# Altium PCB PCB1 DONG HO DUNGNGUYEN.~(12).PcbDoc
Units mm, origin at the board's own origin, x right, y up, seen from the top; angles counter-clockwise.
Board outline 60.96 x 45.72 mm, 2 copper layers (Top Layer, Bottom Layer); 7 components, 8 nets, 31 pads, 0 vias.
Unrouted connection lines stored in the file: 6.
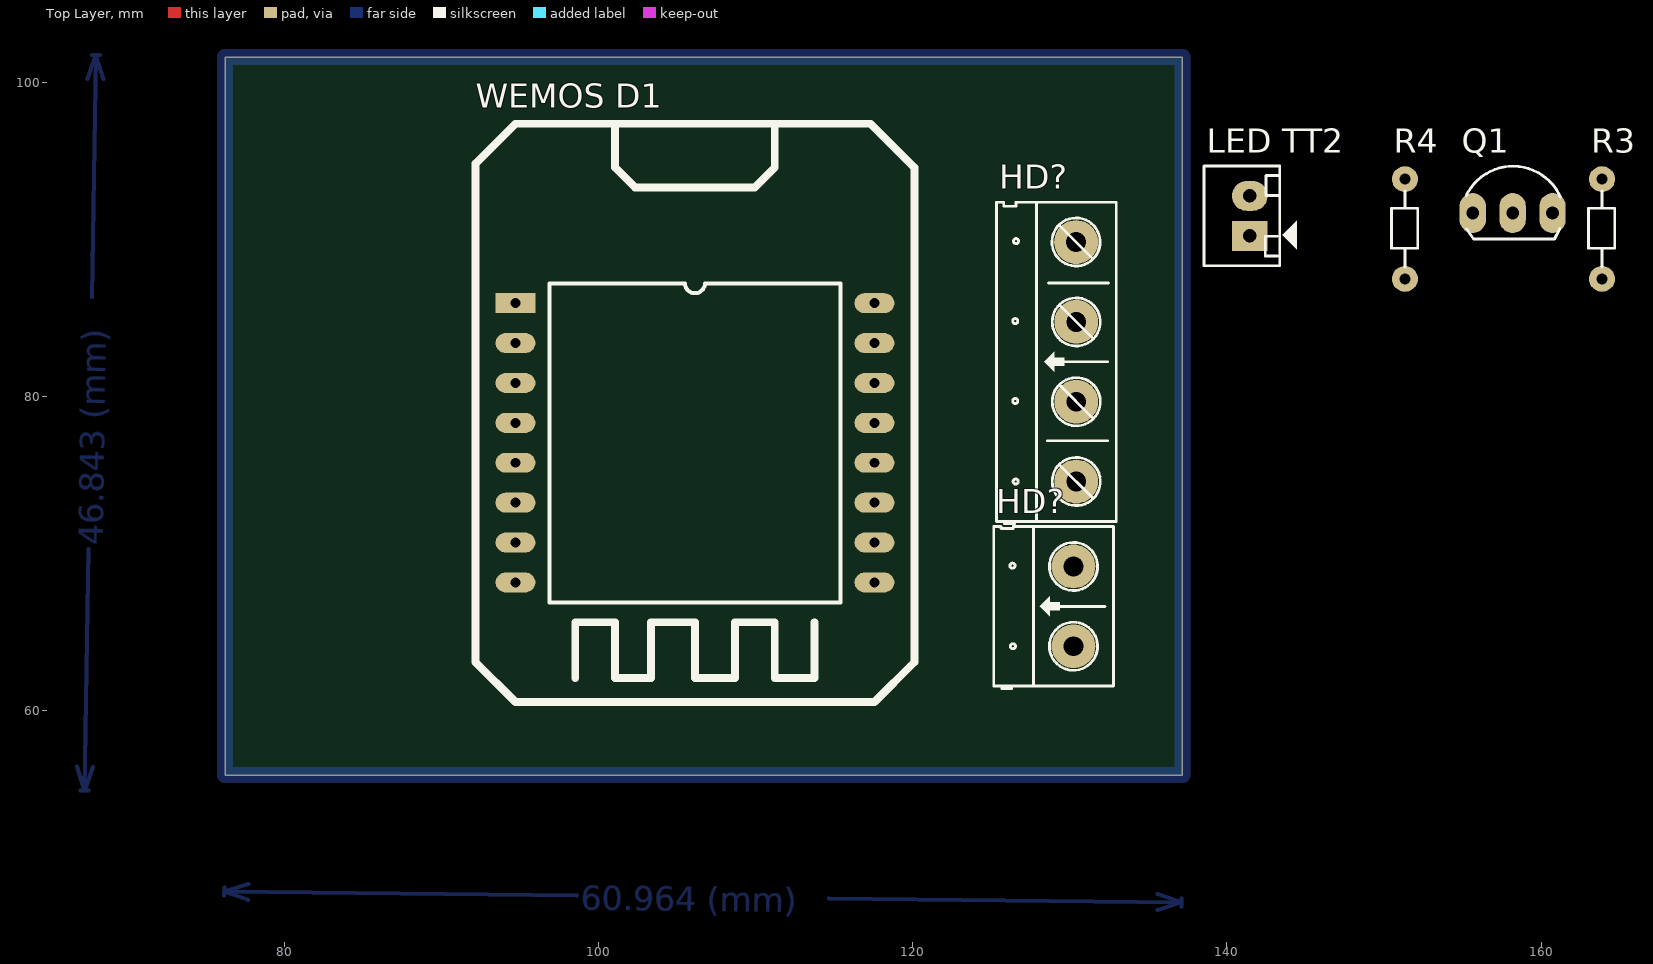
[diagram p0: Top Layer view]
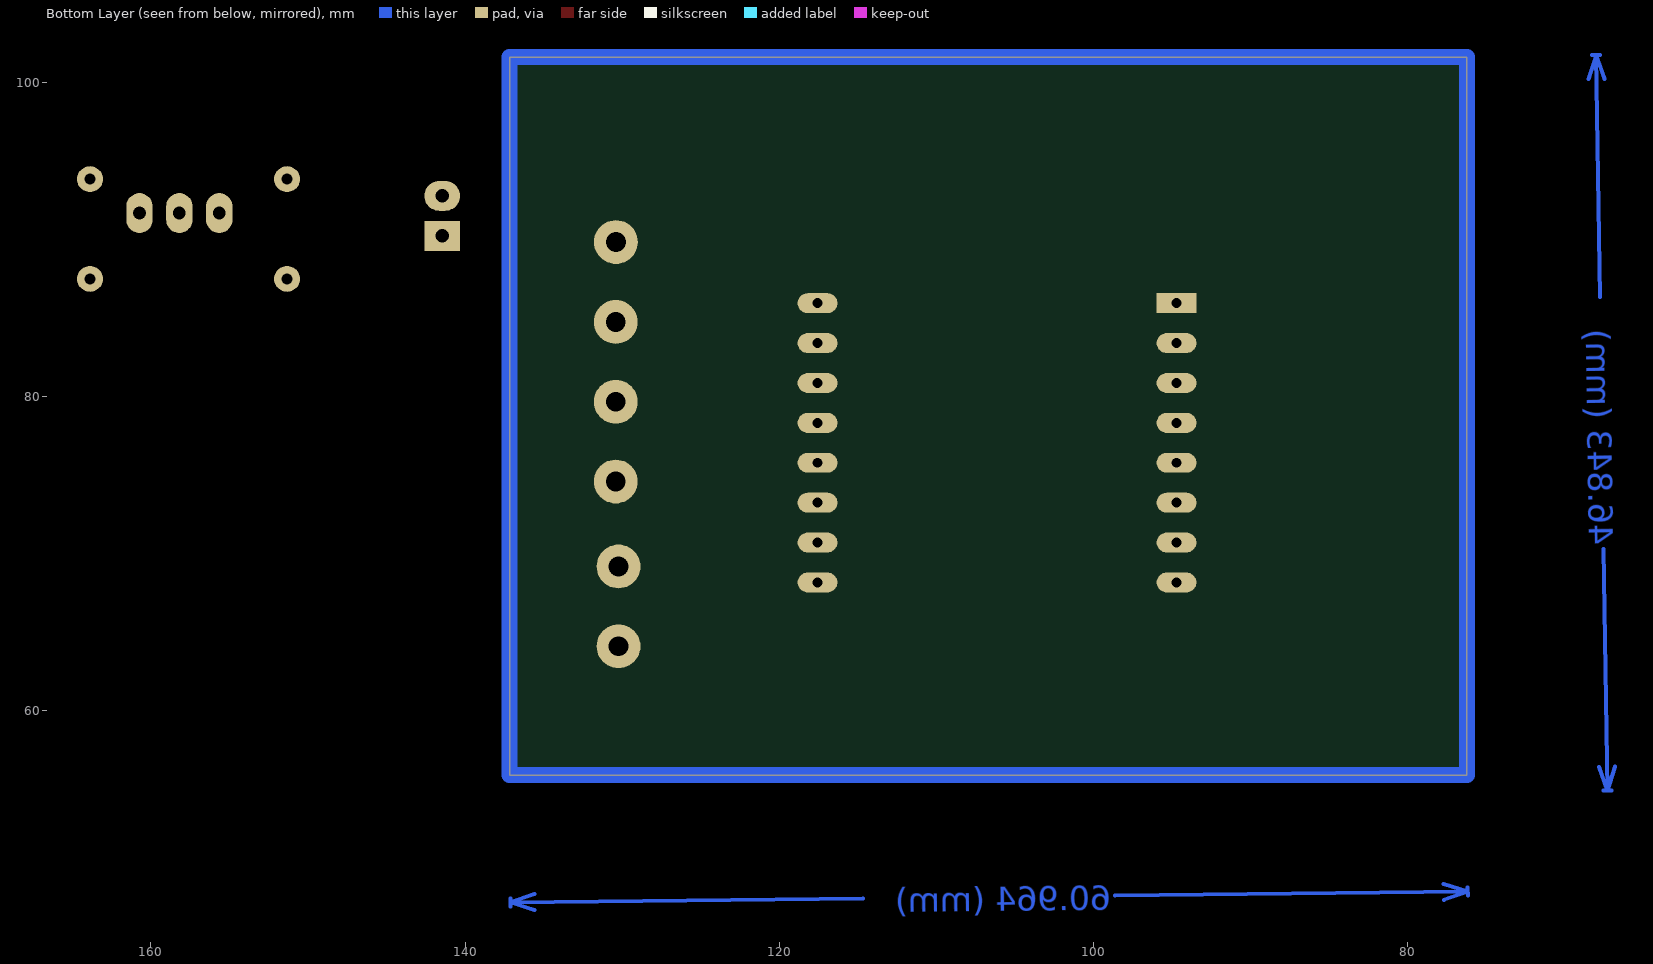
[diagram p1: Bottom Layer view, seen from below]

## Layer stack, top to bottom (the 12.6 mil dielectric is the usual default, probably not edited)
Top Solder: solder mask 0.0102, Solder Resist, Dk 3.5
Top Layer: signal copper 0.0356
Dielectric 1: dielectric 0.32, FR-4, Dk 4.8
Bottom Layer: signal copper 0.0356
Bottom Solder: solder mask 0.0102, Solder Resist, Dk 3.5

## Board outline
76.2,55.88 76.2,101.6 137.16,101.6 137.16,55.88

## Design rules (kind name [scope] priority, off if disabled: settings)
Clearance [All] p1: gap=0.254 ignorepadtopadclearanceinfootprint=FALSE except(0: Arc-Hole Track-Hole SMDPad-Hole THPad-Hole Via-Hole Fill-Hole Poly-Hole Region-Hole Text-Hole)
PolygonConnect [All] p1: connectstyle=Relief reliefconductorwidth=0.254 reliefentries=4 polygonreliefangle="90 Angle" airgapwidth=0.254
RoomDefinition DONG_HO [InComponentClass('DONG_HO')] p1: confinementstyle=ConfineIn formatcopy=TRUE lockcomponents=FALSE outline 138.303,57.277 149.25,57.277 149.25,67.132 138.303,67.132
RoutingVias [All] p1: holewidth=0.711 width=1.27 viastyle="Through Hole" minholewidth=0.711 minwidth=1.27 maxholewidth=2.54 maxwidth=2.54
SolderMaskExpansion [All] p1: expansion=0.102
Width [All] p1: maxlimit=2.032 minlimit=1.016 preferedwidth=1.524
30 further rules are at their usual default settings.

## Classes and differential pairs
component class DONG_HO: HD? "LED TT2" Q1 R3 R4 "WEMOS D1"

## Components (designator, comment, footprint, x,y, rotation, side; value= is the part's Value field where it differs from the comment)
HD? "Header 4" HED4 130.404,74.574 r90 top
HD? "Header 2" HED2 130.226,64.084 r90 top
"LED TT2" "Header2" Header2 141.453,90.221 r90 top
Q1 "C1815" QTO-92 158.191,91.669 r0 top
R3 "100" RES-1/8W-SMALL 163.881,90.653 r90 top
R4 "Res" RES-1/8W-SMALL 151.333,90.653 r90 top
"WEMOS D1" "Component_1" "ESP WEMOS MINI" 94.691,85.928 r0 top

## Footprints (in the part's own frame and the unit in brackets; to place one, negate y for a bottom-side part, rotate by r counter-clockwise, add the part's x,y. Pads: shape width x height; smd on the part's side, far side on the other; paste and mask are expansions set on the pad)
"ESP WEMOS MINI" [mm]
  rect 2.54x1.27 hole 0.635: 1(0,0)
  oval 2.54x1.27 hole 0.635: 2(0,-2.54) 3(0,-5.08) 4(0,-7.62) 5(0,-10.16) 6(0,-12.7) 7(0,-15.24) 8(0,-17.78) 9(22.86,-17.78) 10(22.86,-15.24) 11(22.86,-12.7) 12(22.86,-10.16) 13(22.86,-7.62) 14(22.86,-5.08) 15(22.86,-2.54) 16(22.86,0)
  silkscreen extent -2.54,-25.4 25.4,11.43
Header2 [mil] "CON2"
  rect 75x90 hole 34: 1(0,0)
  oval 75x90 hole 34: 2(100,0)
  silkscreen extent -75,-118 175,115, body extent -68,-70 168,107, height 236
HED2 [mil] "Header 2, 2 pin, hight 300mil, Pin to Pin 200, Colour Green"
  round 110 hole 50: 1(0,0) 2(200,0)
  silkscreen extent -106,-100 300,200, body extent -92,-140 302,155, height 394
HED4 [mil] "Header 4, 4 pin, hight 300mil, Pin to Pin 200, Colour Green"
  round 110 hole 50: 1(0,0) 2(200,0) 3(400.06,0.06) 4(600.39,0.39)
  silkscreen extent -106,-100 700,200
QTO-92 [mil] "TO-92"
  oval 66x100 hole 32: 1(-100,0) 2(0,0) 3(100,0)
  silkscreen extent -117,-65 120,118, body extent -109,-66 109,95, height 245
RES-1/8W-SMALL [mil] "R 1/8W, 2 pin, 200mil"
  round 65 hole 28: 1(-125,0) 2(125,0)
  silkscreen extent -95,-32 95,34, body extent -135,-35 135,37, height 76

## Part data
HD?: library part Hed4, "Header 4 (Green)"
HD?: library part Hed2, "Header 2 (Green)"
"LED TT2": "Header IDC, 2 x 1 Pin Vertical 2.54mm Pitch (Non-Boxed, Male)", Manufacturer="Würth Elektronik eiSos GmbH", partNo=613002143121
Q1: "NPN 600mW, ECB"
R3: library part Res, "Res", Manufacturer="Generic Components"
R4: Manufacturer="Generic Components"

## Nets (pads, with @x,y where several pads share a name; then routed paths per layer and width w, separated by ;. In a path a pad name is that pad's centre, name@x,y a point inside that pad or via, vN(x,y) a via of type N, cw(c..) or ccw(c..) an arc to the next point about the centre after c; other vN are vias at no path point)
D3: "LED TT2.2" "WEMOS D1.4"
D4: "WEMOS D1.3" Q1.3
GND: "WEMOS D1.2" Q1.1 R4.2
"NetLED TT2_1": "LED TT2.1" R4.1
NetQ1_2: Q1.2 R3.1
SCL: "WEMOS D1.6"
SDA: "WEMOS D1.5"
VCC: "WEMOS D1.1"
pads on no net: "WEMOS D1.7" "WEMOS D1.8" "WEMOS D1.9" "WEMOS D1.10" "WEMOS D1.11" "WEMOS D1.12" "WEMOS D1.13" "WEMOS D1.14" "WEMOS D1.15" "WEMOS D1.16" HD?.1 HD?.2 HD?.3 HD?.4 R3.2
copper on no net: | length 304
  Bottom Layer w0.254: 66.774,56.421 67.259,54.889 ; 67.005,54.893 67.513,54.886 ; 67.439,100.211 67.97,101.727 ; 67.493,70.285 67.259,54.889 ; 67.716,101.731 68.224,101.723 ; 67.737,86.331 67.97,101.727 ; 67.79,56.406 67.259,54.889 ; 68.455,100.195 67.97,101.727 ; 76.146,48.209 76.152,48.717 ; 77.667,47.938 76.149,48.463 ; 77.679,48.954 76.149,48.463 ; 98.606,48.211 76.149,48.463 ; 114.653,48.03 137.109,47.777 ; 135.58,47.287 137.109,47.777 ; 135.591,48.303 137.109,47.777 ; 137.106,47.523 137.112,48.031
  Bottom Layer w1.016: 76.2,55.88 137.16,55.88 137.16,101.6 76.2,101.6 76.2,55.88

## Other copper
Bottom Layer:
  text "46.843 (mm)" at 68.411,70.525 h1.52 r89.13
  text "60.964 (mm)" at 98.849,47.294 h1.52 r359.36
